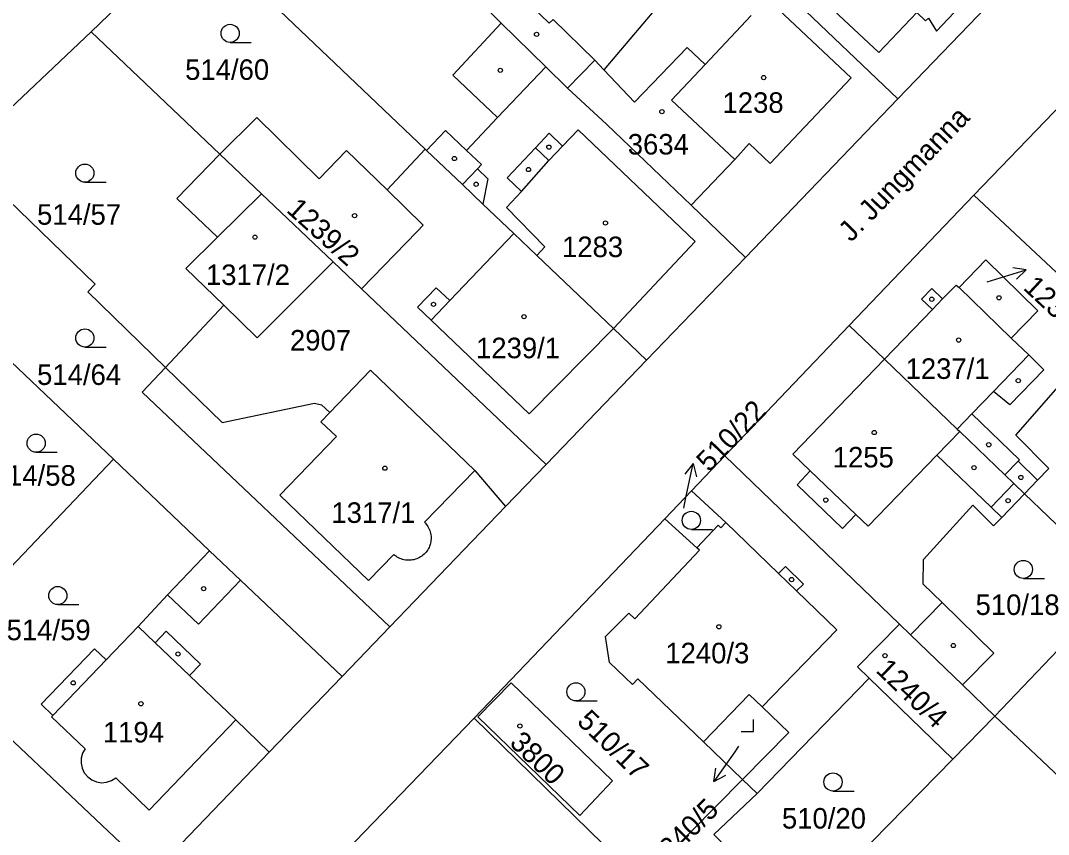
# Model space of a CAD drawing. Extents: x -679220 to -673243, y -1075091 to -1066557.
# Drawn here: x -675968.3 to -675883.3, y -1072103.3 to -1072035.9 of the extents above; entities that cross this region are included whole.
import ezdxf

# ---------------------------------------------------------------- set-up
doc = ezdxf.new("R2010")
doc.units = 0
for name, color, linetype in [('Hranice parcel', 7, 'Continuous'), ('Parcelní čísla', 7, 'Continuous'), ('Pop  PČ popisy', 7, 'Continuous'), ('Vnitřní kresba', 7, 'Continuous'), ('Značky budov', 7, 'Continuous'), ('Značky kultur', 7, 'Continuous')]:
    doc.layers.add(name, color=color, linetype=linetype)

msp = doc.modelspace()

# ---------------------------------------------------------------- linework, layer by layer
at = {"layer": 'Hranice parcel'}
for p, q in [((-675895.73, -1072042.38), (-675933.49, -1072006.37)), ((-675934.84, -1072046.55), (-675953.94, -1072028.36)), ((-675895.73, -1072042.38), (-675884.7, -1072030.92)), ((-675957.19, -1072031.72), (-675962.48, -1072036.83)), ((-675928.55, -1072036.11), (-675930.86, -1072033.84)), ((-675970.95, -1072044.83), (-675962.48, -1072036.83)), ((-675962.48, -1072036.83), (-675951.83, -1072046.97)), ((-675878.99, -1072039.49), (-675889.45, -1072050.36)), ((-675908.35, -1072055.5), (-675895.73, -1072042.38)), ((-675938, -1072049.92), (-675934.84, -1072046.55)), ((-675934.74, -1072046.65), (-675934.84, -1072046.55)), ((-675972.62, -1072047.57), (-675962.16, -1072057.72)), ((-675909.23, -1072047.41), (-675912.85, -1072051.18)), ((-675889.45, -1072050.36), (-675899.77, -1072061.14)), ((-675889.45, -1072050.36), (-675878, -1072061.1)), ((-675912.85, -1072051.18), (-675908.35, -1072055.5)), ((-675916.52, -1072064), (-675908.35, -1072055.5)), ((-675942.47, -1072055.88), (-675940.12, -1072058.11)), ((-675962.16, -1072057.72), (-675962.76, -1072058.35)), ((-675940.12, -1072058.11), (-675924.84, -1072072.65)), ((-675962.76, -1072058.35), (-675956.33, -1072064.61)), ((-675956.33, -1072064.61), (-675951.5, -1072059.47)), ((-675899.77, -1072061.14), (-675910.05, -1072071.93)), ((-675960.63, -1072072.21), (-675969.69, -1072063.6)), ((-675924.84, -1072072.65), (-675916.52, -1072064)), ((-675956.33, -1072064.61), (-675951.63, -1072069.18)), ((-675976.24, -1072088.58), (-675960.63, -1072072.21)), ((-675952.68, -1072079.78), (-675960.63, -1072072.21)), ((-675924.84, -1072072.65), (-675928.19, -1072076.13)), ((-675912.82, -1072074.82), (-675910.05, -1072071.93)), ((-675910.05, -1072071.93), (-675895.61, -1072085.86)), ((-675915.02, -1072077.14), (-675912.82, -1072074.82)), ((-675885.25, -1072075.07), (-675877.39, -1072082.62)), ((-675928.19, -1072076.13), (-675937.76, -1072086.09)), ((-675915.02, -1072077.14), (-675930.8, -1072093.65)), ((-675912.37, -1072079.53), (-675915.02, -1072077.14)), ((-675877.39, -1072082.62), (-675887.71, -1072093.48)), ((-675937.76, -1072086.09), (-675941.72, -1072090.2)), ((-675947.74, -1072096.46), (-675941.72, -1072090.2)), ((-675907.39, -1072099.88), (-675898.12, -1072090.32)), ((-675898.12, -1072090.32), (-675891.18, -1072097.02)), ((-675890.39, -1072090.89), (-675887.71, -1072093.48)), ((-675916.94, -1072107.15), (-675930.8, -1072093.65)), ((-675887.71, -1072093.48), (-675891.18, -1072097.02)), ((-675862.72, -1072117.14), (-675887.71, -1072093.48)), ((-675908.6, -1072098.72), (-675911.82, -1072095.61)), ((-675891.18, -1072097.02), (-675904.11, -1072110.22)), ((-675916.94, -1072107.15), (-675908.6, -1072098.72)), ((-675908.6, -1072098.72), (-675907.39, -1072099.88))]:
    msp.add_line(p, q, dxfattribs=at)
for points in [[(-675903.97, -1072017.71), (-675907.87, -1072021.82), (-675901.79, -1072027.8), (-675901.66, -1072027.93), (-675902.64, -1072028.95), (-675901.66, -1072029.9), (-675903.96, -1072032.3), (-675897.31, -1072038.55), (-675894.16, -1072035.23), (-675893.44, -1072035.92), (-675893.21, -1072035.69), (-675892.55, -1072036.77), (-675890.6, -1072034.73), (-675891.72, -1072034.12), (-675891.49, -1072033.88), (-675892.22, -1072033.19), (-675889.11, -1072029.91), (-675895.6, -1072023.68), (-675894.16, -1072021.95)], [(-675909.23, -1072047.41), (-675908.04, -1072046.08), (-675906.29, -1072047.73), (-675899.59, -1072040.65), (-675906.54, -1072034.08), (-675908.46, -1072032.24), (-675907.88, -1072031.62), (-675909.76, -1072029.85), (-675910.61, -1072029.05), (-675912.53, -1072031.08), (-675920.06, -1072039.99)], [(-675930.86, -1072033.84), (-675928.93, -1072031.91), (-675924.6, -1072036.12), (-675924.25, -1072035.82), (-675920.82, -1072039.19), (-675920.06, -1072039.99)], [(-675928.55, -1072036.11), (-675932.57, -1072040.41), (-675928.85, -1072043.93), (-675931.42, -1072046.65), (-675933.16, -1072044.99), (-675934.74, -1072046.65)], [(-675912.85, -1072051.18), (-675919.82, -1072044.49), (-675923.07, -1072041.49), (-675924.87, -1072039.72), (-675928.55, -1072036.11)], [(-675920.06, -1072039.99), (-675917.52, -1072042.66), (-675913.16, -1072038.13), (-675911.69, -1072039.55), (-675914.47, -1072042.5), (-675909.23, -1072047.41)], [(-675951.83, -1072046.97), (-675948.78, -1072043.92), (-675943.63, -1072049), (-675941.35, -1072046.66), (-675938, -1072049.92)], [(-675951.5, -1072059.47), (-675954.64, -1072056.41), (-675952.03, -1072053.83), (-675955.4, -1072050.62), (-675951.83, -1072046.97)], [(-675951.83, -1072046.97), (-675948.4, -1072050.24), (-675942.47, -1072055.88)], [(-675916.52, -1072064), (-675919.26, -1072061.4), (-675925.61, -1072055.34), (-675927.51, -1072053.53), (-675930.08, -1072051.09), (-675931.77, -1072049.48), (-675934.74, -1072046.65)], [(-675938, -1072049.92), (-675935.01, -1072052.83), (-675935.51, -1072053.35), (-675940.12, -1072058.11)], [(-675884.16, -1072059.92), (-675886.35, -1072062.18), (-675890.67, -1072058), (-675888.45, -1072055.7), (-675884.16, -1072059.92)], [(-675942.47, -1072055.88), (-675948.74, -1072062.15), (-675951.5, -1072059.47)], [(-675899.77, -1072061.14), (-675896.85, -1072063.94), (-675890.83, -1072069.71), (-675890.62, -1072069.91), (-675886.88, -1072073.5), (-675886.13, -1072074.22), (-675885.25, -1072075.07)], [(-675885.25, -1072075.07), (-675884.17, -1072073.94), (-675883.24, -1072072.98), (-675885.97, -1072070.21), (-675878, -1072061.1)], [(-675937.76, -1072086.09), (-675958.26, -1072066.67), (-675956.33, -1072064.61)], [(-675943.41, -1072067.71), (-675942.73, -1072068.34), (-675939.36, -1072064.85), (-675930.73, -1072073.15), (-675928.19, -1072076.13)], [(-675951.63, -1072069.18), (-675943.99, -1072067.57), (-675943.41, -1072067.71)], [(-675912.82, -1072074.82), (-675909.98, -1072077.45), (-675910.39, -1072077.88), (-675910.61, -1072077.67), (-675912.37, -1072079.53)], [(-675890.39, -1072090.89), (-675887.8, -1072088.25), (-675892.08, -1072084.07), (-675893.63, -1072082.55), (-675893.61, -1072080.5), (-675889.53, -1072076.01), (-675887.81, -1072077.73), (-675887.13, -1072077.02), (-675885.25, -1072075.07)], [(-675911.82, -1072095.61), (-675917.25, -1072090.39), (-675917.7, -1072090.85), (-675919.6, -1072089.03), (-675919.92, -1072086.89), (-675918, -1072084.95), (-675917.51, -1072085.41), (-675912.15, -1072079.74), (-675912.37, -1072079.53)], [(-675952.68, -1072079.78), (-675956.16, -1072083.44), (-675958.58, -1072086.05), (-675961.24, -1072088.82), (-675962.2, -1072087.9), (-675966.61, -1072092.49), (-675965.64, -1072093.42), (-675965.75, -1072093.53), (-675962.99, -1072096.17)], [(-675941.72, -1072090.2), (-675950.13, -1072082.21), (-675952.68, -1072079.78)], [(-675898.12, -1072090.32), (-675899.08, -1072089.38), (-675895.61, -1072085.86)], [(-675895.61, -1072085.86), (-675894.69, -1072086.74), (-675890.39, -1072090.89)], [(-675976.24, -1072088.58), (-675969.9, -1072094.63), (-675958.48, -1072105.46)], [(-675922.06, -1072101.69), (-675930.49, -1072093.53), (-675927.72, -1072090.72), (-675919.34, -1072098.83), (-675922.06, -1072101.69)], [(-675911.82, -1072095.61), (-675908.03, -1072091.67), (-675906.95, -1072092.71), (-675904.77, -1072094.82), (-675908.6, -1072098.72)], [(-675960.45, -1072098.59), (-675957.67, -1072101.25), (-675950.51, -1072093.79), (-675947.74, -1072096.46)], [(-675930.8, -1072093.65), (-675948.97, -1072112.49), (-675949, -1072114.48)], [(-675962.99, -1072096.17), (-675963.195, -1072096.537), (-675963.308, -1072096.943), (-675963.321, -1072097.363), (-675963.235, -1072097.775), (-675963.054, -1072098.155), (-675963.039, -1072098.179), (-675962.768, -1072098.501), (-675962.429, -1072098.75), (-675962.041, -1072098.913), (-675961.626, -1072098.979), (-675961.206, -1072098.945), (-675960.807, -1072098.813), (-675960.45, -1072098.59)], [(-675958.48, -1072105.46), (-675956.35, -1072105.41), (-675947.74, -1072096.46)], [(-675907.39, -1072099.88), (-675910.97, -1072103.28), (-675904.11, -1072110.22)]]:
    msp.add_lwpolyline(points, dxfattribs=at)
at = {"layer": 'Pop  PČ popisy'}
for p, q in [((-675887.98, -1072057.42), (-675885.11, -1072056.543)), ((-675885.11, -1072056.543), (-675886.214, -1072056.357)), ((-675885.11, -1072056.543), (-675885.921, -1072057.314)), ((-675888.34, -1072057.53), (-675887.98, -1072057.42)), ((-675912.676, -1072072.575), (-675913.374, -1072073.45)), ((-675913.3, -1072075.51), (-675912.676, -1072072.575)), ((-675912.676, -1072072.575), (-675912.394, -1072073.658)), ((-675913.45, -1072076.25), (-675913.3, -1072075.51)), ((-675909.23, -1072096.42), (-675910.951, -1072098.878)), ((-675908.91, -1072095.96), (-675909.23, -1072096.42)), ((-675910.951, -1072098.878), (-675910.787, -1072097.771)), ((-675910.951, -1072098.878), (-675909.967, -1072098.345))]:
    msp.add_line(p, q, dxfattribs=at)
at = {"layer": 'Vnitřní kresba'}
for p, q in [((-675911.69, -1072039.55), (-675907.86, -1072035.48)), ((-675923.07, -1072041.49), (-675920.82, -1072039.19)), ((-675928.85, -1072043.93), (-675924.87, -1072039.72)), ((-675925.73, -1072046.44), (-675924.6, -1072045.23)), ((-675924.6, -1072045.23), (-675923.49, -1072046.29)), ((-675923.49, -1072046.29), (-675922.2, -1072044.95)), ((-675922.2, -1072044.95), (-675912.5, -1072054.19)), ((-675923.49, -1072046.29), (-675924.62, -1072047.48)), ((-675930.19, -1072047.82), (-675931.42, -1072046.65)), ((-675925.73, -1072046.44), (-675928.07, -1072048.93)), ((-675924.62, -1072047.48), (-675925.73, -1072046.44)), ((-675930.19, -1072047.82), (-675930.52, -1072048.17)), ((-675926.87, -1072050.06), (-675924.62, -1072047.48)), ((-675930.52, -1072048.17), (-675931.77, -1072049.48)), ((-675930.52, -1072048.17), (-675929.66, -1072048.99)), ((-675928.07, -1072048.93), (-675926.87, -1072050.06)), ((-675929.66, -1072048.99), (-675930.08, -1072051.09)), ((-675952.03, -1072053.83), (-675948.4, -1072050.24)), ((-675928.11, -1072051.38), (-675926.87, -1072050.06)), ((-675924.94, -1072054.63), (-675928.11, -1072051.38)), ((-675932.81, -1072059.08), (-675927.51, -1072053.53)), ((-675925.61, -1072055.34), (-675924.94, -1072054.63)), ((-675919.26, -1072061.4), (-675912.5, -1072054.19)), ((-675935.47, -1072059.63), (-675933.93, -1072058.02)), ((-675933.93, -1072058.02), (-675932.81, -1072059.08)), ((-675892.93, -1072058.07), (-675893.77, -1072058.95)), ((-675892.03, -1072058.94), (-675892.93, -1072058.07)), ((-675890.92, -1072057.79), (-675892.03, -1072058.94)), ((-675890.92, -1072057.79), (-675890.67, -1072058)), ((-675934.35, -1072060.69), (-675932.81, -1072059.08)), ((-675893.77, -1072058.95), (-675892.88, -1072059.82)), ((-675892.03, -1072058.94), (-675892.88, -1072059.82)), ((-675934.35, -1072060.69), (-675935.47, -1072059.63)), ((-675892.88, -1072059.82), (-675896.85, -1072063.94)), ((-675926.23, -1072068.46), (-675934.35, -1072060.69)), ((-675919.26, -1072061.4), (-675926.23, -1072068.46)), ((-675886.35, -1072062.18), (-675884.91, -1072063.57)), ((-675896.85, -1072063.94), (-675904.42, -1072071.79)), ((-675887.82, -1072066.59), (-675884.91, -1072063.57)), ((-675884.91, -1072063.57), (-675883.65, -1072064.8)), ((-675883.65, -1072064.8), (-675886.48, -1072067.72)), ((-675889.62, -1072068.46), (-675887.82, -1072066.59)), ((-675886.48, -1072067.72), (-675887.82, -1072066.59)), ((-675943.47, -1072069.11), (-675942.73, -1072068.34)), ((-675890.83, -1072069.71), (-675889.62, -1072068.46)), ((-675889.62, -1072068.46), (-675885.68, -1072072.25)), ((-675943.47, -1072069.11), (-675942.19, -1072070.34)), ((-675890.62, -1072069.91), (-675892.5, -1072071.86)), ((-675942.19, -1072070.34), (-675946.87, -1072075.18)), ((-675904.42, -1072071.79), (-675902.98, -1072073.17)), ((-675892.5, -1072071.86), (-675898.2, -1072077.76)), ((-675892.5, -1072071.86), (-675888.01, -1072076.18)), ((-675885.79, -1072072.37), (-675886.88, -1072073.5)), ((-675885.68, -1072072.25), (-675885.79, -1072072.37)), ((-675885.79, -1072072.37), (-675884.17, -1072073.94)), ((-675930.73, -1072073.15), (-675934.91, -1072077.41)), ((-675902.98, -1072073.17), (-675904.08, -1072074.33)), ((-675902.98, -1072073.17), (-675899.21, -1072076.79)), ((-675904.08, -1072074.33), (-675900.31, -1072077.95)), ((-675888.01, -1072076.18), (-675886.13, -1072074.22)), ((-675939.53, -1072082.24), (-675946.87, -1072075.18)), ((-675900.31, -1072077.95), (-675899.21, -1072076.79)), ((-675899.21, -1072076.79), (-675898.2, -1072077.76)), ((-675887.13, -1072077.02), (-675888.01, -1072076.18)), ((-675905.6, -1072081.68), (-675909.98, -1072077.45)), ((-675937.44, -1072080.09), (-675939.53, -1072082.24)), ((-675905.6, -1072081.68), (-675905.04, -1072081.1)), ((-675905.04, -1072081.1), (-675903.55, -1072082.54)), ((-675904.11, -1072083.11), (-675905.6, -1072081.68)), ((-675950.13, -1072082.21), (-675953.61, -1072085.86)), ((-675903.55, -1072082.54), (-675904.11, -1072083.11)), ((-675953.61, -1072085.86), (-675956.16, -1072083.44)), ((-675900.79, -1072086.32), (-675904.11, -1072083.11)), ((-675894.69, -1072086.74), (-675892.08, -1072084.07)), ((-675958.58, -1072086.05), (-675957.18, -1072087.4)), ((-675906.95, -1072092.71), (-675900.79, -1072086.32)), ((-675957.18, -1072087.4), (-675956.28, -1072086.45)), ((-675956.28, -1072086.45), (-675953.44, -1072089.18)), ((-675957.18, -1072087.4), (-675954.34, -1072090.12)), ((-675965.64, -1072093.42), (-675961.24, -1072088.82)), ((-675953.44, -1072089.18), (-675954.34, -1072090.12)), ((-675954.34, -1072090.12), (-675950.51, -1072093.79))]:
    msp.add_line(p, q, dxfattribs=at)
msp.add_lwpolyline([(-675934.91, -1072077.41), (-675934.827, -1072077.496), (-675934.75, -1072077.587), (-675934.679, -1072077.683), (-675934.615, -1072077.784), (-675934.557, -1072077.888), (-675934.506, -1072077.996), (-675934.462, -1072078.107), (-675934.425, -1072078.221), (-675934.396, -1072078.336), (-675934.374, -1072078.454), (-675934.36, -1072078.572), (-675934.353, -1072078.692), (-675934.355, -1072078.811), (-675934.364, -1072078.93), (-675934.381, -1072079.048), (-675934.405, -1072079.165), (-675934.437, -1072079.28), (-675934.476, -1072079.393), (-675934.523, -1072079.503), (-675934.576, -1072079.61), (-675934.637, -1072079.713), (-675934.704, -1072079.811), (-675934.777, -1072079.906), (-675934.856, -1072079.995), (-675934.941, -1072080.079), (-675935.031, -1072080.158), (-675935.126, -1072080.23), (-675935.225, -1072080.296), (-675935.328, -1072080.356), (-675935.435, -1072080.409), (-675935.546, -1072080.455), (-675935.659, -1072080.493), (-675935.774, -1072080.524), (-675935.891, -1072080.548), (-675936.009, -1072080.564), (-675936.129, -1072080.572), (-675936.248, -1072080.572), (-675936.367, -1072080.565), (-675936.486, -1072080.55), (-675936.603, -1072080.528), (-675936.718, -1072080.498), (-675936.832, -1072080.46), (-675936.942, -1072080.415), (-675937.05, -1072080.363), (-675937.154, -1072080.305), (-675937.254, -1072080.239), (-675937.349, -1072080.168), (-675937.44, -1072080.09)], dxfattribs=at)
at = {"layer": 'Značky budov'}
for centre in [(-675925.627, -1072037.039), (-675928.627, -1072040.019), (-675906.837, -1072040.619), (-675915.257, -1072043.439), (-675924.607, -1072046.379), (-675932.427, -1072047.319), (-675926.297, -1072048.229), (-675930.627, -1072049.449), (-675940.687, -1072052.049), (-675919.927, -1072052.659), (-675948.927, -1072053.829), (-675892.927, -1072058.969), (-675887.367, -1072058.849), (-675934.157, -1072059.389), (-675926.667, -1072060.409), (-675890.707, -1072062.349), (-675885.777, -1072065.709), (-675897.687, -1072069.999), (-675888.217, -1072071.009), (-675889.437, -1072072.909), (-675938.177, -1072072.949), (-675885.557, -1072073.719), (-675901.697, -1072075.589), (-675886.617, -1072075.639), (-675904.527, -1072082.169), (-675953.177, -1072082.919), (-675910.547, -1072086.079), (-675891.147, -1072087.629), (-675955.297, -1072088.329), (-675896.797, -1072088.469), (-675963.967, -1072090.719), (-675958.367, -1072092.449), (-675927.007, -1072094.289)]:
    msp.add_circle(centre, 0.175, dxfattribs=at)
at = {"layer": 'Značky kultur'}
for p, q in [((-675950.983, -1072037.71), (-675949.233, -1072037.71)), ((-675963.003, -1072049.28), (-675961.253, -1072049.28)), ((-675963.003, -1072062.92), (-675961.253, -1072062.92)), ((-675967.033, -1072071.63), (-675965.283, -1072071.63)), ((-675912.823, -1072078.02), (-675911.073, -1072078.02)), ((-675885.353, -1072082.08), (-675883.603, -1072082.08)), ((-675965.243, -1072084.24), (-675963.493, -1072084.24)), ((-675922.373, -1072092.21), (-675920.623, -1072092.21)), ((-675907.69, -1072094.74), (-675907.69, -1072093.74)), ((-675908.691, -1072094.74), (-675907.69, -1072094.74)), ((-675901.103, -1072099.67), (-675899.353, -1072099.67))]:
    msp.add_line(p, q, dxfattribs=at)
for centre in [(-675950.983, -1072036.96), (-675963.003, -1072048.53), (-675963.003, -1072062.17), (-675967.033, -1072070.88), (-675912.823, -1072077.27), (-675885.353, -1072081.33), (-675965.243, -1072083.49), (-675922.373, -1072091.46), (-675901.103, -1072098.92)]:
    msp.add_circle(centre, 0.75, dxfattribs=at)

# ---------------------------------------------------------------- texts
at = {"layer": 'Parcelní čísla'}
for s, p in [('514/60', (-675954.707, -1072040.81)), ('1238', (-675910.244, -1072043.54)), ('3634', (-675918.084, -1072046.989)), ('514/57', (-675966.957, -1072052.8)), ('1283', (-675923.524, -1072055.479)), ('1317/2', (-675952.987, -1072057.79)), ('2907', (-675946.034, -1072063.21)), ('1239/1', (-675930.637, -1072063.85)), ('1237/1', (-675895.097, -1072065.56)), ('514/64', (-675966.957, -1072066.06)), ('1255', (-675901.124, -1072072.89)), ('514/58', (-675970.707, -1072074.4)), ('1317/1', (-675942.607, -1072077.479)), ('510/18', (-675889.307, -1072085.1)), ('514/59', (-675969.477, -1072087.19)), ('1240/3', (-675914.977, -1072089.1)), ('1194', (-675961.514, -1072095.65)), ('510/20', (-675905.327, -1072102.779))]:
    msp.add_text(s, height=1.7, dxfattribs=at).set_placement(p)
for s, rotation, p in [('1239/2', 318, (-675946.412, -1072051.68)), ('1237/2', 317, (-675885.449, -1072058.091)), ('510/22', 46, (-675911.348, -1072073.34)), ('1240/4', 316, (-675897.64, -1072089.759)), ('510/17', 316, (-675922.37, -1072094.009)), ('3800', 316, (-675927.949, -1072095.785)), ('1240/5', 45, (-675915.358, -1072106.257))]:
    msp.add_text(s, height=1.7, rotation=rotation, dxfattribs=at).set_placement(p)
at = {"layer": 'Pop  PČ popisy'}
msp.add_text('J. Jungmanna', height=1.7, rotation=46, dxfattribs=at).set_placement((-675899.601, -1072054.305))

doc.saveas('drawing.dxf')
